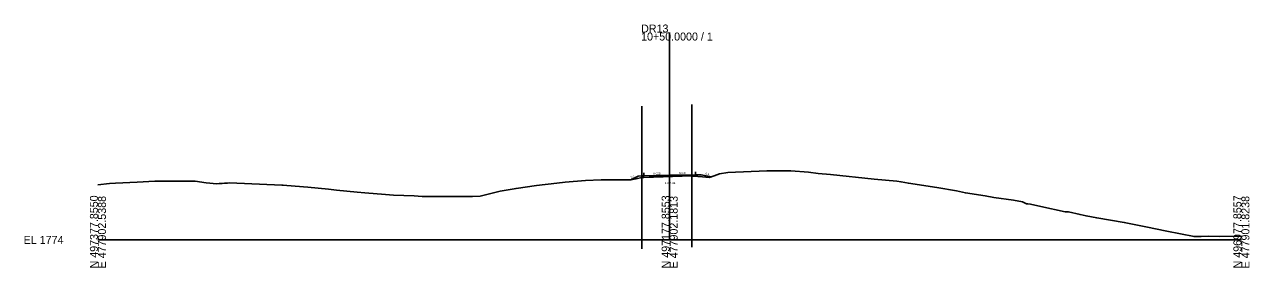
# Model space of a CAD drawing. Extents: x -26 to 403, y -10 to 2160.
# Drawn here: x -25.7 to 402.8, y 490.3 to 575.5 of the extents above; entities that cross this region are included whole.
import ezdxf

# ---------------------------------------------------------------- set-up
doc = ezdxf.new("R2010")
doc.units = 0
for name, color, linetype in [('Exist Cross Section Cell', 7, 'Continuous'), ('Exist XS Center Line Elevation Label', 7, 'Continuous'), ('Exist XS Ground Line', 7, 'Continuous'), ('Prop XS Earthwork Shape', 7, 'Continuous'), ('Prop XS EOT Tick Mark', 7, 'Continuous'), ('Prop XS Finish Grade', 7, 'Continuous'), ('Prop XS Finish Grade Earthwork', 7, 'Continuous'), ('Prop XS Finish Grade Pavement', 7, 'Continuous'), ('Prop XS Pvmt Edge Slope', 7, 'Continuous'), ('Prop XS SE Text', 7, 'Continuous'), ('Prop XS Shoulder Borrow Shape', 7, 'Continuous'), ('Prop XS Side Slope Text', 7, 'Continuous'), ('Prop XS Subgrade Earthwork', 7, 'Continuous'), ('Scratch_Level_1', 7, 'Continuous'), ('Scratch_Level_6', 7, 'Continuous')]:
    doc.layers.add(name, color=color, linetype=linetype)

msp = doc.modelspace()

# ---------------------------------------------------------------- linework, layer by layer
at = {"layer": 'Exist Cross Section Cell'}
for p, q in [((200, 500), (200, 572.71)), ((0, 500), (200, 500)), ((200, 500), (400, 500))]:
    msp.add_line(p, q, dxfattribs=at)
at = {"layer": 'Exist XS Ground Line'}
msp.add_lwpolyline([(0, 519.29), (4.09, 519.75), (6.17, 519.85), (13.69, 520.3), (19.92, 520.55), (30.5, 520.59), (32.39, 520.6), (34, 520.61), (37.85, 520.06), (41.61, 519.72), (42.45, 519.77), (42.95, 519.8), (43.42, 519.83), (44.27, 519.88), (44.65, 519.91), (45.3, 519.94), (46.06, 519.99), (64.3, 519.21), (64.75, 519.2), (66.1, 519.11), (73.4, 518.52), (80.68, 517.76), (83.4, 517.47), (90.67, 516.73), (93.41, 516.49), (100.65, 515.94), (103.41, 515.72), (110.64, 515.45), (113.41, 515.26), (116.2, 515.21), (130.99, 515.26), (133.69, 515.35), (140.73, 517.08), (146.25, 518.04), (153.42, 519.1), (160.56, 519.94), (163.42, 520.28), (170.54, 520.82), (175.98, 521.02), (183.24, 521.06), (186.11, 521.06), (186.51, 521.02), (187.02, 521.16), (188.27, 521.42), (190.32, 521.86), (190.68, 521.86), (192.81, 522.05), (195.21, 522.16), (197.96, 522.26), (199.19, 522.32), (200.28, 522.35), (202.75, 522.45), (205.17, 522.42), (207.72, 522.45), (209.87, 522.25), (211.43, 522.11), (213.79, 521.89), (215.62, 522.52), (217.49, 523.21), (220.39, 523.63), (234.03, 524.24), (242.33, 524.17), (248.58, 523.73), (251.98, 523.31), (256.23, 522.9), (271.5, 521.34), (279.43, 520.63), (280.95, 520.34), (283.54, 519.86), (293.45, 518.33), (300.33, 517.18), (303.45, 516.5), (310.32, 515.48), (313.45, 514.91), (320.3, 513.91), (323.45, 513.37), (324.38, 512.86), (324.84, 512.6), (325.29, 512.66), (326.2, 512.49), (329.9, 511.7), (338.36, 509.89), (339.57, 509.82), (343.6, 508.87), (345.65, 508.4), (349.4, 507.69), (359.01, 506.14), (366.58, 504.57), (373.97, 503.02), (383.48, 501.15), (385.98, 501.25), (388.58, 501.3), (392.39, 501.24), (400, 501.28)], dxfattribs=at)
at = {"layer": 'Prop XS Earthwork Shape'}
for points in [[(186.4, 521.03), (186.51, 521.02), (187.02, 521.16), (188.27, 521.42), (190.32, 521.86), (190.68, 521.86), (191, 521.89), (191, 521.95), (190.45, 521.94), (189.98, 522.41), (189, 522.33)], [(209, 522.31), (207.72, 522.28), (207.72, 522.45), (209.21, 522.31)], [(209.21, 522.31), (209.87, 522.25), (211.43, 522.11), (213.79, 521.89), (214.61, 522.17), (211, 522.77), (210.02, 522.81), (209.53, 522.32)]]:
    msp.add_lwpolyline(points, close=True, dxfattribs=at)
at = {"layer": 'Prop XS EOT Tick Mark'}
for p, q in [((191, 522.49), (191, 523.49)), ((209, 522.85), (209, 523.85))]:
    msp.add_line(p, q, dxfattribs=at)
at = {"layer": 'Prop XS Finish Grade'}
for p, q in [((209, 522.85), (210.02, 522.81)), ((191, 522.49), (189.98, 522.41))]:
    msp.add_line(p, q, dxfattribs=at)
at = {"layer": 'Prop XS Finish Grade Earthwork'}
for p, q in [((189, 522.33), (186.4, 521.03)), ((189.98, 522.41), (189, 522.33)), ((210.02, 522.81), (211, 522.77)), ((211, 522.77), (214.61, 522.17))]:
    msp.add_line(p, q, dxfattribs=at)
at = {"layer": 'Prop XS Finish Grade Pavement'}
for p, q in [((200, 522.67), (209, 522.85)), ((191, 522.49), (200, 522.67))]:
    msp.add_line(p, q, dxfattribs=at)
at = {"layer": 'Prop XS Pvmt Edge Slope'}
for p, q in [((209, 522.85), (209.53, 522.32)), ((191, 522.49), (190.45, 521.94))]:
    msp.add_line(p, q, dxfattribs=at)
at = {"layer": 'Prop XS Shoulder Borrow Shape'}
for points in [[(209.53, 522.32), (210.02, 522.81), (209, 522.85)], [(191, 522.49), (190.45, 521.94), (189.98, 522.41)]]:
    msp.add_lwpolyline(points, close=True, dxfattribs=at)
at = {"layer": 'Prop XS Subgrade Earthwork'}
for p, q in [((190.45, 521.94), (189.98, 522.41)), ((191, 521.95), (190.45, 521.94)), ((191, 521.95), (191, 521.89)), ((207.72, 522.45), (207.72, 522.28)), ((209, 522.31), (207.72, 522.28)), ((209, 522.31), (209.53, 522.32)), ((209.53, 522.32), (210.02, 522.81))]:
    msp.add_line(p, q, dxfattribs=at)
at = {"layer": 'Scratch_Level_1'}
for p, q in [((190.32, 546.86), (190.32, 496.86)), ((207.72, 547.45), (207.72, 497.45))]:
    msp.add_line(p, q, dxfattribs=at)
at = {"layer": 'Scratch_Level_6'}
msp.add_line((191, 521.89), (207.72, 522.45), dxfattribs=at)

# ---------------------------------------------------------------- texts
at = {"layer": 'Exist Cross Section Cell'}
for s, p in [('DR13', (190, 572.71)), ('10+50.0000 / 1', (190, 569.91)), ('EL 1774', (-26, 498.6))]:
    msp.add_text(s, height=2.8, dxfattribs=at).set_placement(p)
for s, p in [('N 497377.8550', (0, 490)), ('E 477902.5388', (2.8, 490)), ('N 497177.8553', (200, 490)), ('E 477902.1813', (202.8, 490)), ('N 496977.8557', (400, 490)), ('E 477901.8238', (402.8, 490))]:
    msp.add_text(s, height=2.8, rotation=90, dxfattribs=at).set_placement(p)
at = {"layer": 'Exist XS Center Line Elevation Label'}
msp.add_text('1796.34', height=0.75, dxfattribs=at).set_placement((198.27, 519.59))
at = {"layer": 'Prop XS SE Text'}
for p in [(194.23, 522.87), (203.23, 523.05)]:
    msp.add_text('0.020', height=0.75, rotation=1.1458, dxfattribs=at).set_placement(p)
at = {"layer": 'Prop XS Side Slope Text'}
for s, rotation, p in [('6:1', 350.5377, (212.51, 522.95)), ('2:1', 26.5651, (186.51, 521.53))]:
    msp.add_text(s, height=0.75, rotation=rotation, dxfattribs=at).set_placement(p)

doc.saveas('drawing.dxf')
